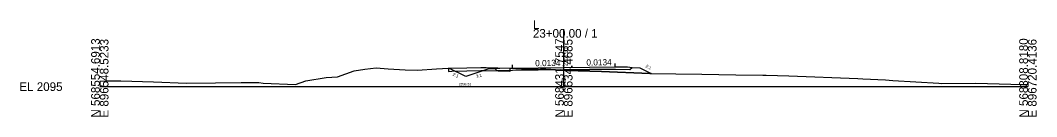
# Model space of a CAD drawing. Extents: x -26 to 1603, y -10 to 13527.
# Drawn here: x -25.7 to 302.8, y 10490.3 to 10521.4 of the extents above; entities that cross this region are included whole.
import ezdxf

# ---------------------------------------------------------------- set-up
doc = ezdxf.new("R2010")
doc.units = 0
for name, color, linetype in [('Default', 7, 'Continuous'), ('Exist XS Center Line Elevation Label', 7, 'Continuous'), ('Exist XS Ground Line', 7, 'Continuous'), ('Old_Level_61', 7, 'Continuous'), ('Old_Level_63', 7, 'Continuous'), ('Prop XS Ditch Slope Text', 7, 'Continuous'), ('Prop XS Ditch Standard Text', 7, 'Continuous'), ('Prop XS Earthwork Shape', 7, 'Continuous'), ('Prop XS EOT Tick Mark', 7, 'Continuous'), ('Prop XS Finish Grade', 7, 'Continuous'), ('Prop XS Finish Grade Earthwork', 7, 'Continuous'), ('Prop XS Finish Grade Paved Shoulder', 7, 'Continuous'), ('Prop XS Finish Grade Pavement', 7, 'Continuous'), ('Prop XS Side Slope Text', 7, 'Continuous'), ('Prop XS Subgrade Earthwork', 7, 'Continuous'), ('Prop XSC Text', 7, 'Continuous')]:
    doc.layers.add(name, color=color, linetype=linetype)

msp = doc.modelspace()

# ---------------------------------------------------------------- linework, layer by layer
at = {"layer": 'Exist XS Ground Line'}
for p, q in [((73.17, 10502.96), (76.83, 10503.2)), ((76.83, 10503.2), (82.25, 10505.14)), ((82.25, 10505.14), (85.67, 10505.62)), ((85.67, 10505.62), (89.32, 10506.04)), ((89.32, 10506.04), (93.22, 10505.72)), ((93.22, 10505.72), (98.69, 10505.43)), ((98.69, 10505.43), (102.64, 10505.32)), ((102.64, 10505.32), (108.85, 10505.76)), ((108.85, 10505.76), (112.72, 10505.93)), ((112.72, 10505.93), (118.59, 10506.08)), ((118.59, 10506.08), (123.2, 10506.2)), ((123.2, 10506.2), (124.91, 10506.17)), ((124.91, 10506.17), (132.57, 10505.98)), ((132.57, 10505.98), (136.29, 10505.72)), ((136.29, 10505.72), (137.45, 10505.68)), ((137.45, 10505.68), (142.43, 10505.76)), ((142.43, 10505.76), (143.82, 10505.77)), ((143.82, 10505.77), (144.15, 10505.75)), ((144.15, 10505.75), (149.65, 10505.35)), ((149.65, 10505.35), (150, 10505.31)), ((150, 10505.31), (150.87, 10505.2)), ((150.87, 10505.2), (162.22, 10504.88)), ((162.22, 10504.88), (177.81, 10504.23)), ((177.81, 10504.23), (194.61, 10504.05)), ((194.61, 10504.05), (205.58, 10503.85)), ((205.58, 10503.85), (214.35, 10503.75)), ((214.35, 10503.75), (215.39, 10503.68)), ((215.39, 10503.68), (222.76, 10503.49)), ((222.76, 10503.49), (244.99, 10502.64)), ((0, 10501.81), (2.19, 10501.83)), ((2.19, 10501.83), (6.75, 10501.88)), ((6.75, 10501.88), (17.34, 10501.53)), ((17.34, 10501.53), (28.03, 10501.1)), ((28.03, 10501.1), (37.37, 10501.23)), ((37.37, 10501.23), (45.73, 10501.32)), ((45.73, 10501.32), (47.47, 10501.36)), ((47.47, 10501.36), (51.37, 10501.31)), ((51.37, 10501.31), (52.81, 10501.13)), ((52.81, 10501.13), (63.21, 10500.7)), ((63.21, 10500.7), (66.61, 10501.88)), ((66.61, 10501.88), (73.17, 10502.96)), ((244.99, 10502.64), (246.63, 10502.53)), ((246.63, 10502.53), (253.93, 10502.17)), ((253.93, 10502.17), (256.35, 10501.97)), ((256.35, 10501.97), (271.26, 10501.08)), ((271.26, 10501.08), (272.08, 10501.04)), ((272.08, 10501.04), (283.12, 10501.07)), ((283.12, 10501.07), (298.27, 10500.68)), ((298.27, 10500.68), (300, 10500.67))]:
    msp.add_line(p, q, dxfattribs=at)
at = {"layer": 'Old_Level_61'}
for p, q in [((112.72, 10505.93), (112.72, 10504.93)), ((112.72, 10504.93), (113.75, 10504.96)), ((113.75, 10504.96), (118.59, 10505.08)), ((118.59, 10505.08), (123.2, 10505.2)), ((123.2, 10505.2), (124.91, 10505.17)), ((124.91, 10505.17), (132.57, 10504.98)), ((132.57, 10504.98), (132.61, 10504.98)), ((132.61, 10504.98), (132.61, 10505.98))]:
    msp.add_line(p, q, dxfattribs=at)
at = {"layer": 'Old_Level_63'}
for p, q in [((150, 10500), (150, 10518.61)), ((0, 10500), (150, 10500)), ((150, 10500), (300, 10500))]:
    msp.add_line(p, q, dxfattribs=at)
at = {"layer": 'Prop XS Earthwork Shape'}
for points in [[(118.36, 10503.25), (112.84, 10505.94), (118.59, 10506.08), (123.2, 10506.2), (124.91, 10506.17), (132.57, 10505.98), (136.29, 10505.72), (137.45, 10505.68), (142.43, 10505.76), (143.82, 10505.77), (144.15, 10505.75), (148.93, 10505.4), (133.43, 10505.2), (128.49, 10505.1), (127.78, 10505.79), (125.43, 10505.61)], [(174.57, 10506.03), (178.18, 10504.23), (177.81, 10504.23), (162.22, 10504.88), (150.87, 10505.2), (150, 10505.31), (149.65, 10505.35), (148.93, 10505.4), (150, 10505.42), (166.57, 10505.64), (171.38, 10505.54), (172.07, 10506.23)]]:
    msp.add_lwpolyline(points, close=True, dxfattribs=at)
at = {"layer": 'Prop XS EOT Tick Mark'}
for p, q in [((133.43, 10505.99), (133.43, 10506.99)), ((166.57, 10506.43), (166.57, 10507.43))]:
    msp.add_line(p, q, dxfattribs=at)
at = {"layer": 'Prop XS Finish Grade'}
for p, q in [((129.32, 10505.91), (127.78, 10505.79)), ((170.57, 10506.35), (172.07, 10506.23))]:
    msp.add_line(p, q, dxfattribs=at)
at = {"layer": 'Prop XS Finish Grade Earthwork'}
for p, q in [((118.36, 10503.25), (112.84, 10505.94)), ((125.43, 10505.61), (118.36, 10503.25)), ((127.78, 10505.79), (125.43, 10505.61)), ((172.07, 10506.23), (174.57, 10506.03)), ((174.57, 10506.03), (178.18, 10504.23))]:
    msp.add_line(p, q, dxfattribs=at)
at = {"layer": 'Prop XS Finish Grade Paved Shoulder'}
for p, q in [((133.43, 10505.99), (129.32, 10505.91)), ((166.57, 10506.43), (170.57, 10506.35))]:
    msp.add_line(p, q, dxfattribs=at)
at = {"layer": 'Prop XS Finish Grade Pavement'}
for p, q in [((133.43, 10505.99), (150, 10506.21)), ((150, 10506.21), (166.57, 10506.43))]:
    msp.add_line(p, q, dxfattribs=at)
at = {"layer": 'Prop XS Subgrade Earthwork'}
for p, q in [((128.49, 10505.1), (127.78, 10505.79)), ((133.43, 10505.2), (128.49, 10505.1)), ((150, 10505.42), (133.43, 10505.2)), ((166.57, 10505.64), (150, 10505.42)), ((166.57, 10505.64), (171.38, 10505.54)), ((171.38, 10505.54), (172.07, 10506.23))]:
    msp.add_line(p, q, dxfattribs=at)

# ---------------------------------------------------------------- texts
at = {"layer": 'Default'}
for p in [(140.73, 10506.58), (157.3, 10506.8)]:
    msp.add_text('0.0134', height=2, rotation=0.7672, dxfattribs=at).set_placement(p)
at = {"layer": 'Exist XS Center Line Elevation Label'}
msp.add_text('2100.31', height=1, rotation=90, dxfattribs=at).set_placement((150.5, 10498.03))
at = {"layer": 'Old_Level_63'}
for s, p in [('L', (140, 10518.61)), ('23+00.00 / 1', (140, 10515.81)), ('EL 2095', (-26, 10498.6))]:
    msp.add_text(s, height=2.8, dxfattribs=at).set_placement(p)
for s, p in [('N 568554.6913', (0, 10490)), ('E 896548.5233', (2.8, 10490)), ('N 568431.7547', (150, 10490)), ('E 896634.4685', (152.8, 10490)), ('N 568308.8180', (300, 10490)), ('E 896720.4136', (302.8, 10490))]:
    msp.add_text(s, height=2.8, rotation=90, dxfattribs=at).set_placement(p)
at = {"layer": 'Prop XS Ditch Slope Text'}
msp.add_text('3:1', height=1, rotation=13.6791, dxfattribs=at).set_placement((121.74, 10502.78))
at = {"layer": 'Prop XS Ditch Standard Text'}
msp.add_text('2098.25', height=0.8, dxfattribs=at).set_placement((116.05, 10500.4))
at = {"layer": 'Prop XS Side Slope Text'}
for rotation, p in [(333.4349, (176.3, 10506.29)), (334.0444, (113.95, 10503.62))]:
    msp.add_text('2:1', height=1, rotation=rotation, dxfattribs=at).set_placement(p)
at = {"layer": 'Prop XSC Text'}
msp.add_text(' 2101.21', height=1.2, rotation=90, dxfattribs=at).set_placement((151.2, 10506.21))

doc.saveas('drawing.dxf')
